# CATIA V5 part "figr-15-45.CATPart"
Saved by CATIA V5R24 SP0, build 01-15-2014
Part number: Part1
Bounding box of the stored display mesh (mm): x 0 to 69.121, y -21.475 to 20.775, z 0 to 47.185
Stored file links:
  D:\KAVITA\CATIA V5-6R2014 Project_ Kavita\CATIA V5-6R2014_partfiles\Partfiles\c15_catia_v5-6r2014_prt\figr-15-45.CATPart
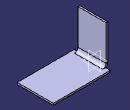
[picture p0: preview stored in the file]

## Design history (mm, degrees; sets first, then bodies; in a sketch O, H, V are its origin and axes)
SheetMetalParameters1: Thickness 2, BendRadius 4, KFactor 0.400515 {= log(min(100,max(20*SheetMetalParameters1.BendRadius,SheetMetalParameters1.Thickness)/SheetMetalParameters1.Thickness))/log(100)/2}, ReliefRadialLength 1, ReliefAxialLength 2, MinimumBendRadius 0
Body1 (main body)
  Sketch1 on xy-plane, origin (0, 0, 0), H (1, 0, 0), V (0, 1, 0)
    line L1 (2.4998, 20.7748) -> (69.1212, 20.7748)
    line L2 (69.1212, 20.7748) -> (69.1212, -21.4753)
    line L3 (69.1212, -21.4753) -> (2.4998, -21.4753)
    line L4 (2.4998, -21.4753) -> (2.4998, 20.7748)
    horizontal: L1 H, L3 H
    vertical: L2 V, L4 V
  Wall1: Thickness 2, Profile Sketch1
  Sketch2 on yz-plane, origin (0, 0, 0), H (0, 1, 0), V (0, 0, 1)
    line L1 (-17.3994, 47.1851) -> (15.4124, 47.1851)
    line L2 (15.4124, 47.1851) -> (15.4124, 3.5135)
    line L3 (15.4124, 3.5135) -> (-17.3994, 3.5135)
    line L4 (-17.3994, 3.5135) -> (-17.3994, 47.1851)
    horizontal: L1 H, L3 H
    vertical: L2 V, L4 V
  Wall2: Thickness 2, Profile Sketch2
  d_Bend1: Bend_BendTable SheetMetalParameters1, Bend_Thickness 2, Bend_KFactor 0.400515 {= log(min(100,max(20*d_Bend1.Bend_KFactorRadius,SheetMetalParameters1.Thickness)/SheetMetalParameters1.Thickness))/log(100)/2}, Bend_FirstSupport Wall1, Bend_SecondSupport Wall2, Bend_KFactorRadius 4 {= d_Bend1.CylindricalBendSurf_Radius}, Bend_Deduction -4.4586 {= (d_Bend1.CylindricalBendSurf_Radius+SheetMetalParameters1.Thickness*d_Bend1.Bend_KFactor)*(PI-abs(d_Bend1.BendSurf_OpenAngle))-2*(d_Bend1.CylindricalBendSurf_Radius+SheetMetalParameters1.Thickness)*tan(min((PI-abs(d_Bend1.BendSurf_OpenAngle)),(PI/2))/2)}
